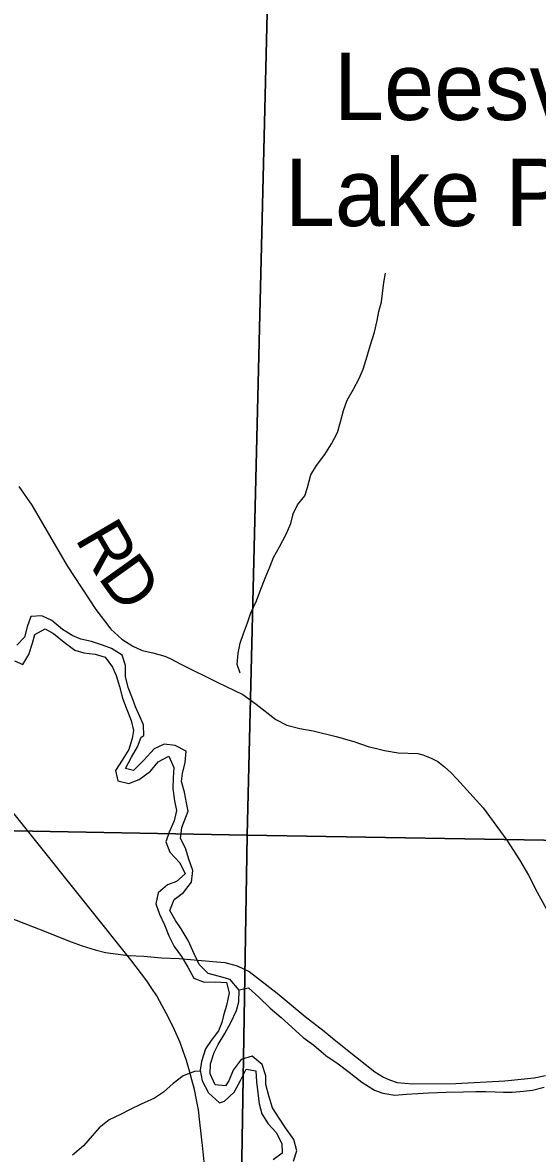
# Model space of a CAD drawing. Extents: x 0 to 34, y 0 to 22.
# Drawn here: x 4.318 to 4.921, y 18.627 to 19.951 of the extents above; entities that cross this region are included whole.
import ezdxf

# ---------------------------------------------------------------- set-up
doc = ezdxf.new("R2010")
doc.units = 0
for name, color, linetype in [('GM_X_Corporation_Text', 7, 'Continuous'), ('GM_X_County_Road', 7, 'Continuous'), ('GM_X_Interchange_Ramps', 7, 'Continuous'), ('GM_X_Interstate_Route', 7, 'Continuous'), ('GM_X_Minor_Lake', 7, 'Continuous'), ('GM_X_Section', 7, 'Continuous'), ('GM_X_Township_Road_Text', 7, 'Continuous'), ('GM_X_US_Location', 7, 'Continuous')]:
    doc.layers.add(name, color=color, linetype=linetype)

msp = doc.modelspace()

# ---------------------------------------------------------------- linework, layer by layer
at = {"layer": 'GM_X_County_Road'}
msp.add_lwpolyline([(4.5325, 18.6015), (4.5294, 18.6325), (4.5259, 18.6635), (4.524, 18.6777), (4.522, 18.6895), (4.5193, 18.7015), (4.5165, 18.7131), (4.5134, 18.7248), (4.51, 18.7355), (4.5063, 18.7464), (4.5025, 18.7566), (4.4961, 18.7716), (4.4887, 18.7867), (4.4816, 18.7997), (4.4752, 18.8113), (4.4694, 18.8198), (4.4637, 18.8287), (4.4449, 18.8536), (4.3317, 18.995), (4.1992, 19.1604)], dxfattribs=at)
at = {"layer": 'GM_X_Interchange_Ramps'}
msp.add_lwpolyline([(4.2423, 18.9265), (4.3195, 18.8965), (4.3437, 18.887), (4.3582, 18.8813), (4.3752, 18.8747), (4.3879, 18.8698), (4.4031, 18.8651), (4.4153, 18.8621), (4.43, 18.8602), (4.4418, 18.8587), (4.4602, 18.8577), (4.4809, 18.856), (4.5014, 18.8549), (4.5411, 18.8517), (4.5549, 18.8503), (4.5693, 18.8466), (4.5834, 18.8397), (4.6161, 18.8144), (4.6492, 18.7873), (4.6714, 18.7698), (4.683, 18.7602), (4.7082, 18.7402), (4.7306, 18.7224), (4.7409, 18.7161), (4.7479, 18.7129), (4.757, 18.71), (4.7748, 18.7084), (4.8257, 18.7087), (4.8828, 18.7119), (4.9171, 18.7154), (4.9304, 18.718)], dxfattribs=at)
at = {"layer": 'GM_X_Interstate_Route'}
msp.add_lwpolyline([(4.3136, 19.4078), (4.329, 19.3859), (4.3705, 19.3148), (4.4038, 19.2636), (4.4214, 19.2407), (4.4342, 19.229), (4.4473, 19.2206), (4.4583, 19.2155), (4.4705, 19.2131), (4.4848, 19.209), (4.491, 19.2064), (4.5042, 19.1994), (4.5469, 19.1781), (4.576, 19.1641), (4.5915, 19.1528), (4.6147, 19.1347), (4.6277, 19.1283), (4.6429, 19.1244), (4.6586, 19.1216), (4.6854, 19.1151), (4.7059, 19.1092), (4.7228, 19.1034), (4.7342, 19.1007), (4.742, 19.0986), (4.758, 19.096), (4.7811, 19.0952), (4.787, 19.0937), (4.7967, 19.0896), (4.8046, 19.0856), (4.8122, 19.0796), (4.8199, 19.0723), (4.8268, 19.0653), (4.8575, 19.0313), (4.8852, 18.9937), (4.9001, 18.9705), (4.9105, 18.9525), (4.9206, 18.9329), (4.9472, 18.8843)], dxfattribs=at)
at = {"layer": 'GM_X_Minor_Lake'}
for points in [[(3.7556, 20.0185), (4.6053, 19.9945), (4.5812, 18.9996), (3.7421, 19.0151), (3.7574, 19.9211)], [(4.6053, 19.9945), (5.6176, 19.9781), (5.6006, 18.9822), (4.5812, 18.9996)], [(3.7421, 19.0151), (4.5812, 18.9996), (4.5642, 17.9795), (3.7264, 17.9888), (3.7408, 18.8998)], [(4.5812, 18.9996), (5.6006, 18.9822), (5.5776, 17.9596), (4.5642, 17.9795)]]:
    msp.add_lwpolyline(points, close=True, dxfattribs=at)
at = {"layer": 'GM_X_Township_Road_Text'}
for points in [[(4.5728, 19.1893), (4.5696, 19.1991), (4.5707, 19.2124), (4.5728, 19.2242), (4.5769, 19.2356), (4.5817, 19.2482), (4.5854, 19.2596), (4.5922, 19.2737), (4.597, 19.2874), (4.6022, 19.3004), (4.6081, 19.3145), (4.6119, 19.3247), (4.619, 19.3369), (4.6268, 19.3518), (4.6324, 19.3644), (4.635, 19.3758), (4.6402, 19.3861), (4.6485, 19.3968), (4.6518, 19.4067), (4.6558, 19.4215), (4.6622, 19.4322), (4.6723, 19.4452), (4.6798, 19.4577), (4.6869, 19.4711), (4.6906, 19.4836), (4.6939, 19.4969), (4.6984, 19.5088), (4.7055, 19.5217), (4.7122, 19.5343), (4.7171, 19.545), (4.7215, 19.5602), (4.7252, 19.5723), (4.7304, 19.5883), (4.7333, 19.602), (4.7355, 19.6127), (4.7384, 19.6241), (4.7398, 19.6339), (4.7412, 19.6465), (4.743, 19.6575)], [(4.5717, 18.8183), (4.5828, 18.8205), (4.595, 18.8096), (4.608, 18.7968), (4.621, 18.7859), (4.6333, 18.7746), (4.6467, 18.7625), (4.6593, 18.7535), (4.6731, 18.7415), (4.6876, 18.7318), (4.7006, 18.722), (4.7155, 18.7104), (4.7304, 18.701), (4.7399, 18.6973), (4.754, 18.6951), (4.7673, 18.696), (4.7809, 18.6969), (4.7935, 18.6977), (4.8041, 18.6982), (4.8143, 18.6987), (4.8345, 18.6988), (4.8489, 18.6993), (4.8607, 18.6994), (4.8717, 18.6988), (4.8812, 18.6985), (4.8915, 18.6986), (4.9047, 18.6998), (4.9154, 18.7007), (4.929, 18.7042)], [(4.5264, 18.7232), (4.5194, 18.7228), (4.5061, 18.7177), (4.4944, 18.7085), (4.4831, 18.6985), (4.4726, 18.6916), (4.4571, 18.6843), (4.4442, 18.6781), (4.4328, 18.6723), (4.4196, 18.6661), (4.4079, 18.6569), (4.3996, 18.6473), (4.3895, 18.6355), (4.3767, 18.6247)]]:
    msp.add_lwpolyline(points, dxfattribs=at)
at = {"layer": 'GM_X_US_Location'}
for points in [[(4.4601, 19.1161), (4.4598, 19.1286), (4.4555, 19.1384), (4.4504, 19.1497), (4.4468, 19.1595), (4.4416, 19.1723), (4.4388, 19.1852), (4.4386, 19.1981), (4.4346, 19.2102), (4.4223, 19.2179), (4.4119, 19.2219), (4.3989, 19.2263), (4.3863, 19.2291), (4.3768, 19.2328), (4.3649, 19.2401), (4.3525, 19.2509), (4.3407, 19.2561), (4.3278, 19.2555), (4.3234, 19.2433), (4.3202, 19.2314), (4.3112, 19.2218)], [(4.3085, 19.2035), (4.3184, 19.1992), (4.3254, 19.211), (4.3298, 19.2244), (4.3323, 19.2343), (4.3447, 19.2409), (4.3543, 19.2354), (4.367, 19.2254), (4.3793, 19.2161), (4.3897, 19.2128), (4.403, 19.2112), (4.4148, 19.208), (4.4234, 19.1963), (4.4277, 19.1865), (4.4317, 19.1737), (4.435, 19.1597), (4.4402, 19.1465), (4.4453, 19.1337), (4.4482, 19.122), (4.4464, 19.1125), (4.4425, 19.0999), (4.4347, 19.0872), (4.4269, 19.0753), (4.4298, 19.0632), (4.4424, 19.06), (4.4548, 19.0648), (4.468, 19.0745), (4.4769, 19.0853), (4.4893, 19.0919), (4.4953, 19.0787), (4.4943, 19.0666), (4.4942, 19.0537), (4.4959, 19.0397), (4.4984, 19.0283), (4.4955, 19.0161), (4.4897, 19.0031), (4.4857, 18.9917), (4.4904, 18.9796), (4.5024, 18.9669), (4.5087, 18.9541), (4.4982, 18.9452), (4.488, 18.9412), (4.4768, 18.9319), (4.4743, 18.919), (4.4783, 18.9069), (4.4842, 18.8945), (4.4894, 18.8817), (4.4957, 18.8692), (4.5042, 18.8572), (4.5117, 18.8448), (4.5187, 18.832), (4.5306, 18.8273), (4.5442, 18.8279), (4.5568, 18.827), (4.56, 18.8149), (4.5569, 18.8), (4.554, 18.7897), (4.5515, 18.7802), (4.5475, 18.7703), (4.5389, 18.7591), (4.5322, 18.7491)], [(4.5557, 18.7059), (4.5436, 18.7072), (4.538, 18.72), (4.5382, 18.7318), (4.5426, 18.7448), (4.547, 18.7543), (4.5551, 18.7674), (4.5621, 18.78), (4.5687, 18.7942), (4.5712, 18.8041), (4.5718, 18.8181), (4.5613, 18.8305), (4.5487, 18.8341), (4.5353, 18.8373), (4.5249, 18.8481), (4.5194, 18.8598), (4.5119, 18.876), (4.5037, 18.8899), (4.4974, 18.8996), (4.4904, 18.9113), (4.4955, 18.9243), (4.5064, 18.9324), (4.5161, 18.9443), (4.5174, 18.958), (4.513, 18.9712), (4.509, 18.9841), (4.5031, 18.9954), (4.5048, 19.0083), (4.5121, 19.0274), (4.51, 19.0372), (4.5079, 19.0497), (4.5043, 19.0622), (4.5056, 19.0717), (4.5085, 19.0846), (4.5098, 19.0979), (4.4967, 19.1046), (4.4838, 19.1059), (4.4721, 19.1004), (4.4601, 19.0873), (4.4482, 19.0753), (4.4386, 19.0774), (4.4456, 19.0908), (4.4527, 19.1027), (4.457, 19.1142), (4.4601, 19.1161)], [(4.5322, 18.7491), (4.5275, 18.7346), (4.5262, 18.7244), (4.5283, 18.7119), (4.5357, 18.6976), (4.5489, 18.686)], [(4.6355, 18.6176), (4.6395, 18.6298), (4.6358, 18.6431), (4.6261, 18.6566), (4.6187, 18.6682), (4.6109, 18.6802), (4.6065, 18.6942), (4.6032, 18.7074), (4.6031, 18.7177), (4.5987, 18.7309), (4.5871, 18.7406), (4.5743, 18.7366), (4.5646, 18.7242), (4.5595, 18.7116), (4.5557, 18.7059)], [(4.5489, 18.686), (4.5545, 18.688), (4.5661, 18.6985), (4.5735, 18.7122), (4.5798, 18.7253), (4.5912, 18.7235), (4.5922, 18.7107), (4.5935, 18.6978), (4.5952, 18.6849), (4.5985, 18.6732), (4.6059, 18.6615), (4.6152, 18.6511), (4.6219, 18.6383), (4.622, 18.6269), (4.6115, 18.6191)]]:
    msp.add_lwpolyline(points, dxfattribs=at)

# ---------------------------------------------------------------- texts
at = {"layer": 'GM_X_Corporation_Text'}
for s, p in [('Leesville', (4.6827, 19.8369)), ('Lake Park', (4.6252, 19.7127))]:
    msp.add_text(s, height=0.07898, rotation=0, dxfattribs=at).set_placement(p)
at = {"layer": 'GM_X_Section'}
for s, rotation, p in [('R', 300.3205, (4.3788, 19.3466)), ('D', 305.6153, (4.4054, 19.3015))]:
    msp.add_text(s, height=0.0568, rotation=rotation, dxfattribs=at).set_placement(p)

doc.saveas('drawing.dxf')
